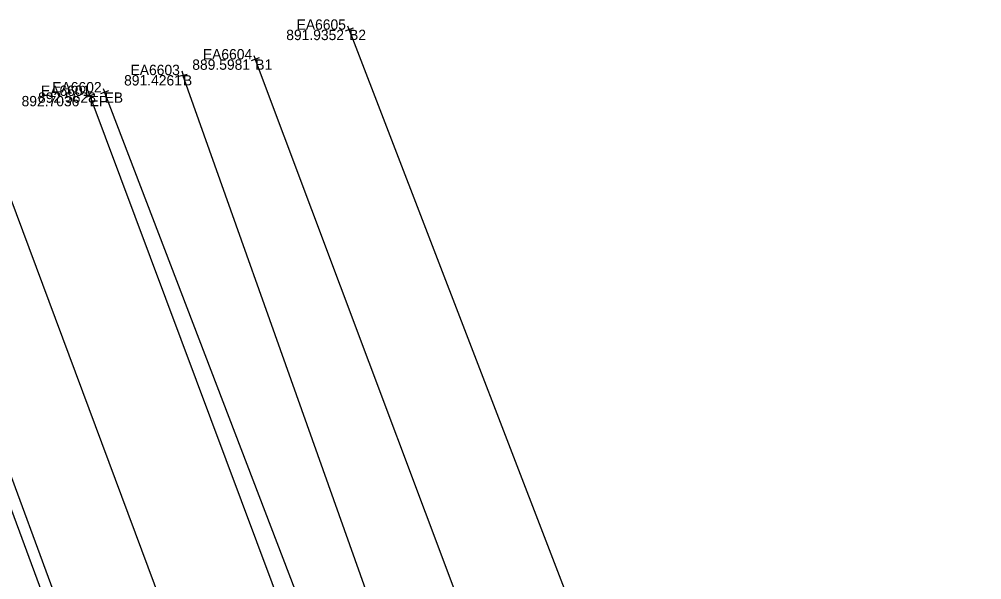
# Model space of a CAD drawing. Extents: x 179044 to 189691, y 286531 to 301257.
# Drawn here: x 180327.9 to 180439.4, y 300712.9 to 300777.8 of the extents above; entities that cross this region are included whole.
import ezdxf

# ---------------------------------------------------------------- set-up
doc = ezdxf.new("R2010")
doc.units = 0
for name, color, linetype in [('PV_X_COP', 7, 'Continuous'), ('PV_X_EOP', 7, 'Continuous'), ('PV_X_Shoulder_Aggregate', 7, 'Continuous'), ('SV_X_Break_Lines', 7, 'Continuous'), ('SV_X_Shot_Marker', 7, 'Continuous'), ('SV_X_Text_Comment', 7, 'Continuous'), ('SV_X_Text_Elevation', 7, 'Continuous'), ('SV_X_Text_Name', 7, 'Continuous')]:
    doc.layers.add(name, color=color, linetype=linetype)

msp = doc.modelspace()

# ---------------------------------------------------------------- linework, layer by layer
at = {"layer": 'PV_X_COP'}
msp.add_lwpolyline([(180435.29, 300467.37), (180412.88, 300528.12), (180394.43, 300576.01), (180387.7, 300594.07), (180373.61, 300631.85), (180356.6, 300677.34), (180322.12, 300769.7)], dxfattribs=at)
at = {"layer": 'PV_X_EOP'}
for points in [[(180336.02, 300768.96), (180371.12, 300675.18), (180391.48, 300627.03), (180401.14, 300618.13), (180409.94, 300612.3), (180420.83, 300608.19), (180437.01, 300607.02), (180453.78, 300606.87), (180491.75, 300607.1)], [(180345.73, 300673.8), (180312.19, 300764.8)]]:
    msp.add_lwpolyline(points, dxfattribs=at)
at = {"layer": 'PV_X_Shoulder_Aggregate'}
for points in [[(180337.75, 300769.37), (180373.5, 300675.95), (180393.39, 300628.4), (180402.34, 300620.16), (180411.15, 300613.97), (180421.2, 300610.61), (180436.88, 300608.74)], [(180344.4, 300673.8), (180311.06, 300764.05)]]:
    msp.add_lwpolyline(points, dxfattribs=at)
at = {"layer": 'SV_X_Break_Lines'}
for points in [[(180366.08, 300776.63), (180398.51, 300692.41)], [(180355.21, 300773.19), (180388.06, 300685.64), (180409.75, 300627.7)], [(180415.96, 300645.51), (180421.02, 300638.43), (180430.45, 300633.44), (180433.6, 300627.02), (180431.18, 300621.21), (180421.09, 300619.3), (180408.16, 300622.51), (180398.65, 300630.3), (180379.34, 300679.91), (180346.83, 300771.37)]]:
    msp.add_lwpolyline(points, dxfattribs=at)
at = {"layer": 'SV_X_Shot_Marker'}
for p, q in [((180366.55, 300776.81), (180365.61, 300776.45)), ((180365.9, 300777.1), (180366.26, 300776.16)), ((180366.08, 300776.63), (180366.08, 300776.63)), ((180355.68, 300773.37), (180354.74, 300773.02)), ((180355.03, 300773.66), (180355.38, 300772.72)), ((180355.21, 300773.19), (180355.21, 300773.19)), ((180346.35, 300771.24), (180347.31, 300771.5)), ((180346.7, 300771.85), (180346.96, 300770.89)), ((180346.83, 300771.37), (180346.83, 300771.37)), ((180336.49, 300769.14), (180335.55, 300768.79)), ((180335.84, 300769.43), (180336.19, 300768.5)), ((180336.02, 300768.96), (180336.02, 300768.96)), ((180338.22, 300769.55), (180337.29, 300769.2)), ((180337.58, 300769.84), (180337.93, 300768.91)), ((180337.75, 300769.37), (180337.75, 300769.37))]:
    msp.add_line(p, q, dxfattribs=at)

# ---------------------------------------------------------------- texts
at = {"layer": 'SV_X_Text_Comment'}
for s, p in [('B2', (180366.08, 300775.43)), ('B1', (180355.21, 300771.99)), ('B', (180346.83, 300770.17)), ('EP', (180336.02, 300767.76)), ('EB', (180337.75, 300768.17))]:
    msp.add_text(s, height=1.2, dxfattribs=at).set_placement(p)
at = {"layer": 'SV_X_Text_Elevation'}
for s, p in [('891.9352', (180358.8, 300775.43)), ('889.5981', (180347.91, 300771.99)), ('891.4261', (180340.01, 300770.17)), ('892.7036', (180328.13, 300767.76)), ('892.5628', (180330.04, 300768.17))]:
    msp.add_text(s, height=1.2, dxfattribs=at).set_placement(p)
at = {"layer": 'SV_X_Text_Name'}
for s, p in [('EA6605', (180360, 300776.63)), ('EA6604', (180349.14, 300773.19)), ('EA6603', (180340.76, 300771.37)), ('EA6601', (180330.38, 300768.96)), ('EA6602', (180331.69, 300769.37))]:
    msp.add_text(s, height=1.2, dxfattribs=at).set_placement(p)

doc.saveas('drawing.dxf')
